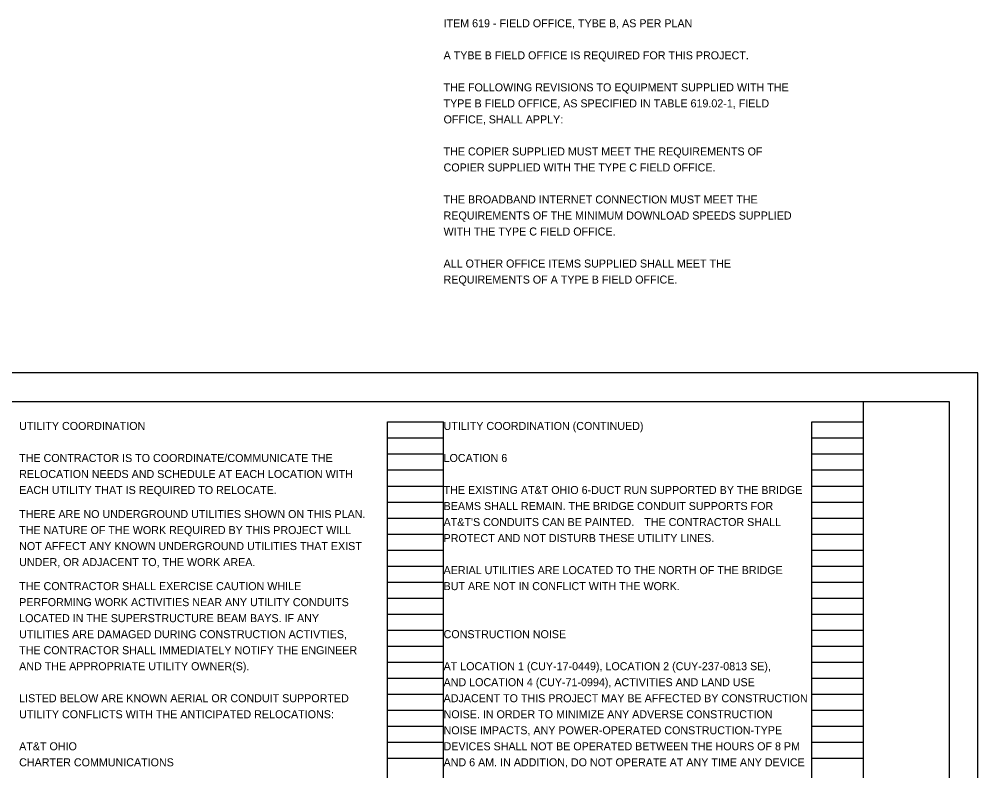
# Model space of a CAD drawing. Extents: x 0 to 34, y -14.6 to 28.2.
# Drawn here: x 17.24 to 34, y 15.04 to 28.18 of the extents above; entities that cross this region are included whole.
import ezdxf

# ---------------------------------------------------------------- set-up
doc = ezdxf.new("R2010")
doc.units = 0
for name, color, linetype in [('SH_Border', 7, 'Continuous'), ('SH_Cut_Line', 7, 'Continuous'), ('SH_Data', 7, 'Continuous'), ('SH_Text', 7, 'Continuous')]:
    doc.layers.add(name, color=color, linetype=linetype)

msp = doc.modelspace()

# ---------------------------------------------------------------- linework, layer by layer
at = {"layer": 'SH_Border'}
msp.add_line((32, 0.5), (32, 21.5), dxfattribs=at)
msp.add_lwpolyline([(1.5, 21.5), (33.5, 21.5), (33.5, 0.5), (1.5, 0.5)], close=True, dxfattribs=at)
at = {"layer": 'SH_Cut_Line'}
msp.add_lwpolyline([(0, 0), (34, 0), (34, 22), (0, 22)], close=True, dxfattribs=at)
at = {"layer": 'SH_Data'}
for p, q in [((23.68, 0.98), (23.68, 21.14)), ((23.68, 21.14), (24.66, 21.14)), ((24.66, 0.98), (24.66, 21.14)), ((31.1, 0.98), (31.1, 21.14)), ((31.1, 21.14), (32, 21.14)), ((32, 0.98), (32, 21.14)), ((23.68, 20.86), (24.66, 20.86)), ((31.1, 20.86), (32, 20.86)), ((23.68, 20.58), (24.66, 20.58)), ((31.1, 20.58), (32, 20.58)), ((23.68, 20.3), (24.66, 20.3)), ((31.1, 20.3), (32, 20.3)), ((23.68, 20.02), (24.66, 20.02)), ((31.1, 20.02), (32, 20.02)), ((23.68, 19.74), (24.66, 19.74)), ((31.1, 19.74), (32, 19.74)), ((23.68, 19.46), (24.66, 19.46)), ((31.1, 19.46), (32, 19.46)), ((23.68, 19.18), (24.66, 19.18)), ((31.1, 19.18), (32, 19.18)), ((23.68, 18.9), (24.66, 18.9)), ((31.1, 18.9), (32, 18.9)), ((23.68, 18.62), (24.66, 18.62)), ((31.1, 18.62), (32, 18.62)), ((23.68, 18.34), (24.66, 18.34)), ((31.1, 18.34), (32, 18.34)), ((23.68, 18.06), (24.66, 18.06)), ((31.1, 18.06), (32, 18.06)), ((23.68, 17.78), (24.66, 17.78)), ((31.1, 17.78), (32, 17.78)), ((23.68, 17.5), (24.66, 17.5)), ((31.1, 17.5), (32, 17.5)), ((23.68, 17.22), (24.66, 17.22)), ((31.1, 17.22), (32, 17.22)), ((23.68, 16.94), (24.66, 16.94)), ((31.1, 16.94), (32, 16.94)), ((23.68, 16.66), (24.66, 16.66)), ((31.1, 16.66), (32, 16.66)), ((23.68, 16.38), (24.66, 16.38)), ((31.1, 16.38), (32, 16.38)), ((23.68, 16.1), (24.66, 16.1)), ((31.1, 16.1), (32, 16.1)), ((23.68, 15.82), (24.66, 15.82)), ((31.1, 15.82), (32, 15.82)), ((23.68, 15.54), (24.66, 15.54)), ((31.1, 15.54), (32, 15.54)), ((23.68, 15.26), (24.66, 15.26)), ((31.1, 15.26), (32, 15.26))]:
    msp.add_line(p, q, dxfattribs=at)

# ---------------------------------------------------------------- texts
at = {"layer": 'SH_Text'}
for s, p in [('ITEM 619 - FIELD OFFICE, TYBE B, AS PER PLAN', (24.66, 28.039)), ('A TYBE B FIELD OFFICE IS REQUIRED FOR THIS PROJECT.', (24.66, 27.479)), ('THE FOLLOWING REVISIONS TO EQUIPMENT SUPPLIED WITH THE', (24.66, 26.919)), ('TYPE B FIELD OFFICE, AS SPECIFIED IN TABLE 619.02-1, FIELD', (24.66, 26.639)), ('OFFICE, SHALL APPLY:', (24.66, 26.359)), ('THE COPIER SUPPLIED MUST MEET THE REQUIREMENTS OF', (24.66, 25.799)), ('COPIER SUPPLIED WITH THE TYPE C FIELD OFFICE.', (24.66, 25.519)), ('THE BROADBAND INTERNET CONNECTION MUST MEET THE', (24.66, 24.959)), ('REQUIREMENTS OF THE MINIMUM DOWNLOAD SPEEDS SUPPLIED', (24.66, 24.679)), ('WITH THE TYPE C FIELD OFFICE.', (24.66, 24.399)), ('ALL OTHER OFFICE ITEMS SUPPLIED SHALL MEET THE', (24.66, 23.839)), ('REQUIREMENTS OF A TYPE B FIELD OFFICE.', (24.66, 23.559)), ('UTILITY COORDINATION', (17.24, 21)), ('UTILITY COORDINATION (CONTINUED)', (24.66, 21)), ('THE CONTRACTOR IS TO COORDINATE/COMMUNICATE THE ', (17.24, 20.44)), ('LOCATION 6', (24.66, 20.44)), ('RELOCATION NEEDS AND SCHEDULE AT EACH LOCATION WITH ', (17.24, 20.16)), ('EACH UTILITY THAT IS REQUIRED TO RELOCATE.', (17.24, 19.88)), ('THE EXISTING AT&T OHIO 6-DUCT RUN SUPPORTED BY THE BRIDGE ', (24.66, 19.88)), ('BEAMS SHALL REMAIN. THE BRIDGE CONDUIT SUPPORTS FOR ', (24.66, 19.6)), ('THERE ARE NO UNDERGROUND UTILITIES SHOWN ON THIS PLAN.', (17.24, 19.46)), ("AT&T'S CONDUITS CAN BE PAINTED. ", (24.66, 19.32)), ('THE CONTRACTOR SHALL ', (28.168, 19.32)), ('THE NATURE OF THE WORK REQUIRED BY THIS PROJECT WILL', (17.24, 19.18)), ('PROTECT AND NOT DISTURB THESE UTILITY LINES.', (24.66, 19.04)), ('NOT AFFECT ANY KNOWN UNDERGROUND UTILITIES THAT EXIST', (17.24, 18.9)), ('UNDER, OR ADJACENT TO, THE WORK AREA.', (17.24, 18.62)), ('AERIAL UTILITIES ARE LOCATED TO THE NORTH OF THE BRIDGE ', (24.66, 18.48)), ('THE CONTRACTOR SHALL EXERCISE CAUTION WHILE ', (17.24, 18.2)), ('BUT ARE NOT IN CONFLICT WITH THE WORK.', (24.66, 18.2)), ('PERFORMING WORK ACTIVITIES NEAR ANY UTILITY CONDUITS', (17.24, 17.92)), ('LOCATED IN THE SUPERSTRUCTURE BEAM BAYS. IF ANY', (17.24, 17.64)), ('UTILITIES ARE DAMAGED DURING CONSTRUCTION ACTIVTIES,', (17.24, 17.36)), ('CONSTRUCTION NOISE', (24.66, 17.36)), ('THE CONTRACTOR SHALL IMMEDIATELY NOTIFY THE ENGINEER', (17.24, 17.08)), ('AND THE APPROPRIATE UTILITY OWNER(S).', (17.24, 16.8)), ('AT LOCATION 1 (CUY-17-0449), LOCATION 2 (CUY-237-0813 SE),', (24.66, 16.8)), ('AND LOCATION 4 (CUY-71-0994), ACTIVITIES AND LAND USE ', (24.66, 16.52)), ('LISTED BELOW ARE KNOWN AERIAL OR CONDUIT SUPPORTED', (17.24, 16.24)), ('ADJACENT TO THIS PROJECT MAY BE AFFECTED BY CONSTRUCTION ', (24.66, 16.24)), ('UTILITY CONFLICTS WITH THE ANTICIPATED RELOCATIONS:', (17.24, 15.96)), ('NOISE. IN ORDER TO MINIMIZE ANY ADVERSE CONSTRUCTION ', (24.66, 15.96)), ('NOISE IMPACTS, ANY POWER-OPERATED CONSTRUCTION-TYPE ', (24.66, 15.68)), ('AT&T OHIO', (17.24, 15.4)), ('DEVICES SHALL NOT BE OPERATED BETWEEN THE HOURS OF 8 PM ', (24.66, 15.4)), ('CHARTER COMMUNICATIONS', (17.24, 15.12)), ('AND 6 AM. IN ADDITION, DO NOT OPERATE AT ANY TIME ANY DEVICE ', (24.66, 15.12))]:
    msp.add_text(s, height=0.14, dxfattribs=at).set_placement(p)

doc.saveas('drawing.dxf')
